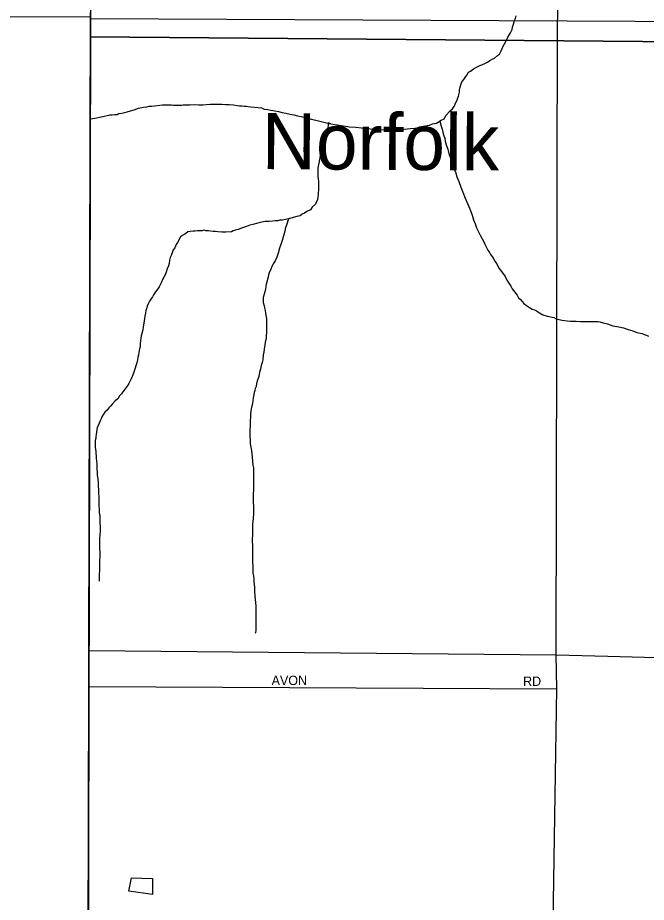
# Model space of a CAD drawing. Extents: x 2010165 to 2382125, y 1060529 to 1407316.
# Drawn here: x 2113583 to 2116938, y 1262787 to 1267507 of the extents above; entities that cross this region are included whole.
import ezdxf

# ---------------------------------------------------------------- set-up
doc = ezdxf.new("R2010")
doc.units = 0
for name, color, linetype in [('GM_X_Adjacent_County', 7, 'Continuous'), ('GM_X_City_Street', 7, 'Continuous'), ('GM_X_City_Street_Text', 7, 'Continuous'), ('GM_X_Corporation', 7, 'Continuous'), ('GM_X_County', 7, 'Continuous'), ('GM_X_Interstate_Route', 7, 'Continuous'), ('GM_X_Minor_Lake', 7, 'Continuous'), ('GM_X_Minor_River', 7, 'Continuous'), ('GM_X_Rail_Line', 7, 'Continuous'), ('GM_X_Rail_Line_Text', 7, 'Continuous')]:
    doc.layers.add(name, color=color, linetype=linetype)

msp = doc.modelspace()

# ---------------------------------------------------------------- linework, layer by layer
at = {"layer": 'GM_X_Adjacent_County'}
msp.add_lwpolyline([(2113401.8, 1277801), (2113713.6, 1277682.4), (2113866.9, 1277540.8), (2113869.4, 1277446.4), (2113925.9, 1277406.6), (2114036.3, 1277407.2), (2114028.2, 1277067.2), (2113991.2, 1275520.7), (2113984.5, 1272833.3), (2113971.4, 1267533.5), (2113963, 1264130), (2113962.6, 1263937.9), (2113955.8, 1261185.2), (2113953.5, 1260222.9), (2113939.6, 1254280.1)], dxfattribs=at)
at = {"layer": 'GM_X_City_Street'}
for points in [[(2116464.5, 1267467), (2116465.1, 1267525), (2116467.9, 1267647.2), (2116487.6, 1268493.4), (2116492.2, 1268687.3), (2116498.1, 1269038.7), (2116504.5, 1269419.7), (2116516.9, 1270152.2), (2116550.8, 1272077), (2116556.8, 1272422.1), (2116559, 1272542.9), (2116566.7, 1272843.5), (2116570.2, 1273148.5), (2116574.6, 1273527.5), (2116584.4, 1274380.4), (2116589.8, 1274845.8)], [(2116420.1, 1261333.2), (2116431.7, 1262110.4), (2116460.7, 1263925.9), (2116456.3, 1264106.2), (2116464.5, 1267466.7), (2116464.5, 1267467)], [(2113962.5, 1263937.9), (2116460.7, 1263925.9)]]:
    msp.add_lwpolyline(points, dxfattribs=at)
at = {"layer": 'GM_X_Corporation'}
msp.add_lwpolyline([(2087103.1, 1267526.8), (2100292, 1267571.3), (2105566.3, 1267515.2), (2113972.1, 1267511.1), (2113971.4, 1267404), (2113929.8, 1250070.4), (2113906.2, 1245908.9), (2107567, 1245842.9), (2100580.4, 1245842), (2087018.7, 1245699)], close=True, dxfattribs=at)
for points in [[(2140205.4, 1267168.3), (2121968.1, 1267337), (2113971.4, 1267404), (2113972.1, 1267511.1)], [(2113929.8, 1250070.4), (2113971.4, 1267404), (2121968.1, 1267337), (2140205.4, 1267168.3), (2140069, 1257837), (2140063.6, 1257468.8), (2140046.9, 1256760.6)]]:
    msp.add_lwpolyline(points, dxfattribs=at)
at = {"layer": 'GM_X_County'}
msp.add_lwpolyline([(2113939.6, 1254280.1), (2113953.5, 1260222.9), (2113955.8, 1261185.2), (2113962.6, 1263937.9), (2113963, 1264130), (2113971.4, 1267533.5)], dxfattribs=at)
at = {"layer": 'GM_X_Interstate_Route'}
for points in [[(2113963, 1264130), (2116456.3, 1264106.2), (2116731.7, 1264099.2)], [(2116731.7, 1264099.2), (2117383, 1264082.7), (2117478.7, 1264080.3), (2117972.6, 1264067.8), (2119067.8, 1263982)]]:
    msp.add_lwpolyline(points, dxfattribs=at)
at = {"layer": 'GM_X_Minor_Lake'}
for points in [[(2114244.8, 1262915.7), (2114302.3, 1262913.8), (2114302.6, 1262827.5), (2114176.2, 1262845.2), (2114190, 1262917.5)], [(2114190, 1262917.5), (2114244.8, 1262915.7)]]:
    msp.add_lwpolyline(points, dxfattribs=at)
at = {"layer": 'GM_X_Minor_River'}
for points in [[(2115917.5, 1267044.5), (2115921.4, 1267054.6), (2115927.4, 1267066.6), (2115931.4, 1267078.7), (2115935.4, 1267088.7), (2115941.3, 1267108.8), (2115941.3, 1267120.8), (2115943.3, 1267130.9), (2115945.2, 1267142.9), (2115953.2, 1267165), (2115963.2, 1267177.1), (2115971.2, 1267187.2), (2115979.1, 1267199.2), (2115989.1, 1267215.3), (2115999.1, 1267221.4), (2116015.1, 1267233.4), (2116031.2, 1267243.5), (2116049.2, 1267251.6), (2116059.2, 1267255.7), (2116079.3, 1267263.8), (2116089.3, 1267269.8), (2116103.3, 1267277.9), (2116115.3, 1267285.9), (2116127.3, 1267290), (2116143.3, 1267304.1), (2116153.3, 1267312.1), (2116163.3, 1267330.2), (2116173.3, 1267354.3), (2116181.2, 1267366.4), (2116189.2, 1267382.5), (2116199.2, 1267402.6), (2116207.2, 1267416.7), (2116213.1, 1267426.7), (2116221.1, 1267442.8), (2116223.1, 1267456.8), (2116229, 1267472.9), (2116235, 1267491), (2116239, 1267503.1), (2116242.9, 1267517.1)], [(2113974.2, 1266967.1), (2113995.3, 1266970.1), (2114029.4, 1266978.3), (2114053.4, 1266982.4), (2114075.5, 1266988.5), (2114087.5, 1266988.5), (2114101.6, 1266990.6), (2114113.6, 1266990.6), (2114123.6, 1266994.6), (2114139.7, 1266996.7), (2114153.7, 1267000.8), (2114167.7, 1267004.8), (2114185.8, 1267008.9), (2114203.8, 1267015), (2114227.9, 1267023.1), (2114254, 1267029.2), (2114272, 1267031.2), (2114284, 1267035.3), (2114298.1, 1267035.3), (2114356.2, 1267041.5), (2114374.3, 1267041.6), (2114390.4, 1267041.6), (2114404.4, 1267041.7), (2114414.5, 1267039.7), (2114426.5, 1267039.8), (2114438.5, 1267039.8), (2114456.6, 1267039.9), (2114466.6, 1267041.9), (2114480.7, 1267041.9), (2114502.7, 1267042), (2114526.8, 1267044.1), (2114548.9, 1267042.2), (2114571, 1267042.2), (2114589, 1267044.3), (2114611.1, 1267044.4), (2114635.2, 1267044.4), (2114655.2, 1267044.5), (2114673.3, 1267044.6), (2114691.4, 1267042.6), (2114711.4, 1267042.7), (2114735.5, 1267040.8), (2114753.6, 1267038.8), (2114767.6, 1267036.8), (2114779.7, 1267036.9), (2114791.7, 1267034.9), (2114803.8, 1267034.9), (2114813.8, 1267033), (2114827.9, 1267031), (2114845.9, 1267029.1), (2114866, 1267027.1), (2114884.1, 1267025.2), (2114898.1, 1267019.2), (2114918.2, 1267017.2), (2114934.3, 1267013.3), (2114954.4, 1267009.3), (2114974.4, 1267005.4), (2114994.5, 1267001.4), (2115014.6, 1266997.5), (2115036.7, 1266991.6), (2115056.8, 1266987.6), (2115076.9, 1266983.6), (2115094.9, 1266979.7), (2115117, 1266973.7), (2115149.2, 1266965.8), (2115173.3, 1266959.9), (2115195.4, 1266953.9), (2115223.5, 1266948), (2115253.6, 1266940.1), (2115354, 1266924.3), (2115388.1, 1266922.4), (2115418.2, 1266918.5), (2115446.3, 1266916.6), (2115472.4, 1266912.7), (2115504.5, 1266912.8), (2115520.6, 1266910.8), (2115540.7, 1266908.9), (2115558.7, 1266908.9), (2115576.8, 1266909), (2115596.9, 1266907.1), (2115614.9, 1266909.1), (2115633, 1266909.2), (2115647, 1266911.2), (2115663.1, 1266913.3), (2115679.1, 1266915.3), (2115703.2, 1266917.4), (2115715.2, 1266919.5), (2115727.2, 1266923.5), (2115737.3, 1266925.6), (2115749.3, 1266927.6), (2115767.4, 1266931.7), (2115781.4, 1266933.7), (2115797.4, 1266939.8), (2115807.5, 1266941.8), (2115817.5, 1266943.9), (2115843.5, 1266960), (2115859.5, 1266966.1), (2115869.5, 1266986.2), (2115889.5, 1267008.3), (2115903.5, 1267020.4), (2115911.5, 1267032.5), (2115917.5, 1267044.5)], [(2115253.6, 1266940.1), (2115239.5, 1266946), (2115239.6, 1266930), (2115233.7, 1266907.9), (2115227.7, 1266891.8), (2115223.7, 1266877.8), (2115219.8, 1266855.7), (2115213.8, 1266837.6), (2115207.9, 1266819.5), (2115205.9, 1266803.5), (2115202, 1266785.4), (2115198, 1266769.3), (2115194.1, 1266749.2), (2115190.1, 1266731.2), (2115186.2, 1266715.1), (2115184.2, 1266701.1), (2115184.2, 1266685), (2115184.3, 1266671), (2115184.3, 1266658.9), (2115186.4, 1266646.9), (2115188.5, 1266632.8), (2115188.5, 1266616.8), (2115188.5, 1266606.8), (2115188.6, 1266596.7), (2115188.6, 1266584.7), (2115186.6, 1266574.6), (2115186.7, 1266562.6), (2115184.7, 1266548.6), (2115182.8, 1266536.5), (2115172.8, 1266512.4), (2115154.8, 1266496.3), (2115144.8, 1266482.2), (2115126.8, 1266472.1), (2115112.8, 1266464.1), (2115100.8, 1266458), (2115090.8, 1266449.9), (2115072.7, 1266445.9), (2115028.2, 1266432.6), (2114996.5, 1266425.6), (2114982.5, 1266425.5), (2114970.4, 1266423.5), (2114956.4, 1266423.4), (2114942.4, 1266421.4), (2114924.3, 1266419.3), (2114904.2, 1266419.2), (2114886.2, 1266415.2), (2114864.1, 1266411.1), (2114838.1, 1266403), (2114822, 1266398.9), (2114804, 1266392.8), (2114781.9, 1266384.8), (2114759.9, 1266376.6), (2114745.9, 1266372.6), (2114733.8, 1266368.5), (2114723.8, 1266364.5), (2114693.7, 1266362.4), (2114671.7, 1266362.3), (2114651.6, 1266364.3), (2114639.5, 1266366.2), (2114625.5, 1266366.2), (2114611.4, 1266368.1), (2114601.4, 1266370.1), (2114587.3, 1266370.1), (2114577.3, 1266372.1), (2114567.3, 1266370), (2114551.2, 1266370), (2114541.2, 1266369.9), (2114529.2, 1266367.9), (2114519.1, 1266367.8), (2114503.1, 1266365.8), (2114491, 1266363.8), (2114481, 1266355.7), (2114471, 1266349.6), (2114451, 1266339.5), (2114445, 1266323.5), (2114435.1, 1266307.4), (2114429.1, 1266297.3), (2114421.1, 1266279.2), (2114413.1, 1266267.2), (2114409.1, 1266257.1), (2114401.2, 1266237), (2114397.2, 1266227), (2114393.2, 1266212.9), (2114391.3, 1266194.9), (2114387.3, 1266182.8), (2114381.4, 1266166.8), (2114375.4, 1266148.7), (2114371.4, 1266138.6), (2114363.4, 1266122.6), (2114357.5, 1266112.5), (2114349.5, 1266092.4), (2114343.5, 1266080.4), (2114337.5, 1266070.3), (2114331.6, 1266060.2), (2114323.6, 1266050.2), (2114315.6, 1266038.1), (2114307.6, 1266028.1), (2114301.6, 1266018), (2114293.6, 1266003.9), (2114285.6, 1265993.9), (2114281.7, 1265983.8)], [(2115835.8, 1266955.2), (2115843.6, 1266927.9), (2115847.7, 1266911.9), (2115851.8, 1266895.8), (2115857.8, 1266875.8), (2115861.9, 1266863.8), (2115864, 1266847.7), (2115870.1, 1266827.6), (2115878.2, 1266805.6), (2115884.3, 1266781.6), (2115892.4, 1266757.5), (2115900.5, 1266733.4), (2115906.6, 1266715.4), (2115912.7, 1266697.4), (2115918.7, 1266683.3), (2115926.8, 1266657.3), (2115937, 1266633.2), (2115947.1, 1266603.2), (2115959.2, 1266575.1), (2115971.4, 1266543.1), (2115983.5, 1266515), (2115993.6, 1266490.9), (2116001.7, 1266472.9), (2116007.8, 1266452.9), (2116015.9, 1266428.8), (2116024, 1266406.8), (2116032.1, 1266384.7), (2116044.3, 1266360.7), (2116052.3, 1266342.6), (2116062.4, 1266326.6), (2116068.5, 1266314.6), (2116076.6, 1266298.6), (2116084.7, 1266280.6), (2116092.7, 1266266.5), (2116100.8, 1266254.5), (2116106.9, 1266242.5), (2116121, 1266224.5), (2116127.1, 1266208.4), (2116139.1, 1266192.4), (2116149.2, 1266174.4), (2116183.5, 1266126.4), (2116193.6, 1266106.3), (2116203.7, 1266090.3), (2116213.8, 1266074.3), (2116221.9, 1266060.3), (2116234, 1266044.2), (2116248.1, 1266026.2), (2116256.2, 1266012.2), (2116266.2, 1266002.2), (2116284.4, 1265982.2), (2116298.5, 1265970.2), (2116314.5, 1265960.2), (2116328.6, 1265952.2), (2116340.7, 1265948.3), (2116350.7, 1265942.3), (2116366.8, 1265932.3), (2116384.9, 1265920.3), (2116409, 1265914.4), (2116427.1, 1265910.4), (2116443.2, 1265906.5), (2116457.2, 1265900.5), (2116473.3, 1265896.5), (2116487.4, 1265892.6), (2116501.4, 1265890.6), (2116515.5, 1265888.6), (2116531.5, 1265886.7), (2116547.6, 1265886.7), (2116563.6, 1265886.8), (2116585.7, 1265884.8), (2116603.8, 1265884.9), (2116617.8, 1265884.9), (2116629.9, 1265885), (2116643.9, 1265885), (2116655.9, 1265885.1), (2116668, 1265885.1), (2116678, 1265885.1), (2116690.1, 1265883.2), (2116708.1, 1265879.2), (2116730.2, 1265873.3), (2116758.4, 1265863.3), (2116790.5, 1265857.4), (2116816.6, 1265851.5), (2116840.7, 1265843.5), (2116864.8, 1265835.6), (2116886.9, 1265827.6), (2116913, 1265821.7), (2116933.1, 1265813.7), (2116949.2, 1265807.8)], [(2115028.2, 1266432.6), (2115016.7, 1266399.5), (2115012.7, 1266387.5), (2115008.8, 1266367.4), (2115000.8, 1266343.3), (2114994.9, 1266317.2), (2114986.9, 1266297.1), (2114981, 1266277), (2114973, 1266250.9), (2114965.1, 1266228.8), (2114957.1, 1266208.7), (2114947.2, 1266192.6), (2114939.2, 1266178.6), (2114933.2, 1266164.5), (2114925.3, 1266144.4), (2114921.3, 1266134.4), (2114919.3, 1266122.3), (2114915.3, 1266112.3), (2114913.4, 1266096.2), (2114909.4, 1266084.2), (2114907.4, 1266070.1), (2114905.5, 1266060.1), (2114901.5, 1266044), (2114897.6, 1266032), (2114893.6, 1266013.9), (2114893.7, 1265987.8), (2114897.8, 1265969.8), (2114899.8, 1265957.7), (2114903.9, 1265943.7), (2114905.9, 1265929.6), (2114908, 1265917.6), (2114910, 1265901.6), (2114910.1, 1265889.5), (2114910.1, 1265871.5), (2114910.2, 1265859.4), (2114910.2, 1265843.4), (2114910.3, 1265827.3), (2114908.3, 1265811.3), (2114908.4, 1265795.2), (2114904.5, 1265775.1), (2114902.5, 1265759.1), (2114898.6, 1265739), (2114896.6, 1265720.9), (2114892.7, 1265706.9), (2114890.7, 1265680.8), (2114886.8, 1265666.7), (2114882.8, 1265650.7), (2114878.9, 1265630.6), (2114872.9, 1265614.5), (2114869, 1265592.4), (2114863, 1265572.3), (2114857.1, 1265554.3), (2114855.1, 1265538.2), (2114851.1, 1265528.2), (2114849.2, 1265518.1), (2114845.2, 1265506.1), (2114841.2, 1265488), (2114839.3, 1265477.9), (2114837.3, 1265463.9), (2114835.4, 1265445.8), (2114831.4, 1265427.8), (2114827.5, 1265407.7), (2114825.5, 1265391.6), (2114825.6, 1265375.6), (2114823.6, 1265357.5), (2114823.7, 1265341.4), (2114823.8, 1265323.4), (2114821.8, 1265309.3), (2114821.8, 1265299.3), (2114821.9, 1265285.3), (2114821.9, 1265269.2), (2114824, 1265255.2), (2114824, 1265243.1), (2114824.1, 1265233.1), (2114830.2, 1265197), (2114832.3, 1265176.9), (2114834.3, 1265160.9), (2114836.4, 1265138.8), (2114838.5, 1265118.8), (2114840.6, 1265104.7), (2114840.6, 1265090.7), (2114840.7, 1265070.6), (2114840.8, 1265050.6), (2114840.8, 1265034.5), (2114840.8, 1265022.5), (2114840.9, 1265008.4), (2114840.9, 1264998.4), (2114841, 1264984.3), (2114839, 1264970.3), (2114839.1, 1264958.2), (2114839.1, 1264946.2), (2114839.1, 1264934.2), (2114839.2, 1264918.1), (2114841.3, 1264902.1), (2114841.3, 1264882), (2114841.4, 1264861.9), (2114839.5, 1264835.8), (2114837.5, 1264815.8)], [(2114281.7, 1265983.8), (2114273.7, 1265967.8), (2114271.7, 1265957.7), (2114267.7, 1265943.7), (2114265.8, 1265929.6), (2114261.8, 1265913.6), (2114259.9, 1265901.5), (2114257.9, 1265889.4), (2114252, 1265855.3), (2114250, 1265841.3), (2114246.1, 1265821.2), (2114242.1, 1265809.1), (2114240.2, 1265797.1), (2114238.2, 1265783.1), (2114236.2, 1265769), (2114236.3, 1265752.9), (2114232.3, 1265738.9), (2114230.4, 1265720.8), (2114228.4, 1265706.8), (2114224.5, 1265694.7), (2114222.5, 1265680.7), (2114218.5, 1265664.6), (2114214.6, 1265654.6), (2114208.6, 1265630.4), (2114200.7, 1265610.3), (2114194.7, 1265592.3), (2114188.7, 1265580.2), (2114182.8, 1265568.2), (2114176.8, 1265554.1), (2114166.8, 1265540), (2114150.8, 1265519.9), (2114144.8, 1265509.8), (2114136.8, 1265499.8), (2114126.8, 1265489.7), (2114116.9, 1265473.6), (2114102.9, 1265461.6), (2114088.9, 1265445.5), (2114078.9, 1265433.4), (2114068.9, 1265425.3), (2114060.9, 1265413.3), (2114048.9, 1265401.2), (2114040.9, 1265391.1), (2114032.9, 1265377.1), (2114028.9, 1265367), (2114023, 1265354.9), (2114007, 1265318.8), (2114005.1, 1265308.7), (2114003.1, 1265296.7), (2114001.1, 1265282.6), (2113999.2, 1265272.6), (2113999.2, 1265262.6), (2113997.2, 1265250.5), (2113997.3, 1265238.5), (2113997.3, 1265224.4), (2113997.4, 1265212.4), (2113999.4, 1265194.3), (2113999.5, 1265180.3), (2114001.5, 1265170.3), (2114001.6, 1265156.2), (2114003.6, 1265140.2), (2114005.7, 1265126.1), (2114005.7, 1265112.1), (2114005.8, 1265098.1), (2114007.8, 1265082), (2114007.9, 1265063.9), (2114010, 1265045.9), (2114012.1, 1265025.8), (2114012.1, 1265007.8), (2114014.2, 1264987.7), (2114014.3, 1264969.7), (2114016.3, 1264947.6), (2114016.4, 1264923.5), (2114016.5, 1264901.4), (2114018.6, 1264883.4), (2114018.6, 1264867.3), (2114020.7, 1264847.3), (2114020.8, 1264829.2), (2114020.8, 1264811.2), (2114022.9, 1264791.1), (2114023, 1264769), (2114021.1, 1264746.9), (2114019.1, 1264728.9), (2114019.2, 1264714.8), (2114019.2, 1264704.8), (2114019.2, 1264688.8), (2114019.3, 1264672.7), (2114021.4, 1264656.6), (2114021.4, 1264646.6), (2114021.5, 1264632.6), (2114019.5, 1264608.5), (2114019.6, 1264594.4), (2114019.6, 1264580.4), (2114019.7, 1264564.3), (2114017.8, 1264528.2), (2114017.8, 1264518.2), (2114017.9, 1264506.1), (2114017.9, 1264500.1)], [(2114837.5, 1264815.8), (2114835.6, 1264803.7), (2114835.6, 1264793.7), (2114835.7, 1264773.6), (2114835.7, 1264759.6), (2114835.8, 1264743.5), (2114833.8, 1264725.5), (2114833.9, 1264709.4), (2114836, 1264693.4), (2114836, 1264677.3), (2114836.1, 1264661.3), (2114836.1, 1264647.2), (2114836.2, 1264633.2), (2114836.2, 1264619.1), (2114836.3, 1264597.1), (2114838.4, 1264581), (2114838.5, 1264556.9), (2114838.5, 1264542.9), (2114840.6, 1264528.8), (2114842.6, 1264510.8), (2114842.7, 1264498.8), (2114844.7, 1264482.7), (2114846.8, 1264466.7), (2114846.9, 1264446.6), (2114849, 1264420.5), (2114853.1, 1264368.4), (2114853.2, 1264348.3), (2114853.3, 1264326.2), (2114853.4, 1264308.1), (2114853.4, 1264294.1), (2114853.5, 1264280.1), (2114853.5, 1264270), (2114853.6, 1264237.9), (2114851.6, 1264223.9), (2114849.6, 1264221.9)]]:
    msp.add_lwpolyline(points, dxfattribs=at)
at = {"layer": 'GM_X_Rail_Line'}
msp.add_lwpolyline([(2113972.9, 1267502.1), (2117240.2, 1267485.7), (2117936.8, 1267482.1), (2118637, 1267476.4), (2119207.2, 1267469.2), (2120788.3, 1267454.9), (2122004.3, 1267442.8), (2123412.6, 1267429.2), (2125388.1, 1267409.2), (2126127.6, 1267400.6), (2127231.4, 1267389.9), (2130406.6, 1267359.9), (2132736.5, 1267337.1), (2134810.6, 1267317.8), (2139871.2, 1267271.3), (2143552.9, 1267237)], dxfattribs=at)

# ---------------------------------------------------------------- texts
at = {"layer": 'GM_X_City_Street_Text'}
for s, p in [('AVON', (2114938, 1263945.7)), ('RD', (2116280, 1263941.3))]:
    msp.add_text(s, height=50, rotation=0, dxfattribs=at).set_placement(p)
at = {"layer": 'GM_X_Rail_Line_Text'}
msp.add_text('Norfolk', height=299, rotation=359.674, dxfattribs=at).set_placement((2114885, 1266698.7))

doc.saveas('drawing.dxf')
